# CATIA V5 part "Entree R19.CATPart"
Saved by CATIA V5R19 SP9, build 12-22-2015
Part number: entree
Bounding box of the stored display mesh (mm): x -13.996 to 13.996, y -15 to 21.5, z -13.996 to 13.996
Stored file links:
  C:\Users\hbezard\Documents\Perso\imprimante 3d\pieces\rincepot\Entree R19 - Copie.CATPart
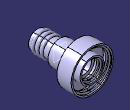
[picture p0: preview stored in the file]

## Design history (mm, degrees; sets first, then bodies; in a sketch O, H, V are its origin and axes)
Parameters
  `dia admi` = 22
  `dia evac` = 10
  `paroies hp` = 2
  `paroies bp` = 2
  `longueur filetee` = 5
  `pas jonction` = 2
  `prof filet jonction` = 1
  `dia gourde` = 12
  `pas gourde` = 2
  `entree gourde` = 8
  `longueur jonction` = 30
  `dia injection` = 8
  `longueur injection` = 110
  `longueur gourde` = 30
  `dia inter injection` = 6
  Real = 0
Body1 (main body)
  Sketch1 on yz-plane, origin (0, 0, 0), H (0, 1, 0), V (0, 0, 1)
    line L1 (-15, 6) -> (-13, 6)
    line L2 (0, 6) -> (0, 8)
    line L3 (16, 8) -> (21.5, 8)
    line L4 (21.5, 8) -> (21.5, 7)
    line L5 (21.5, 7) -> (16, 7)
    line L6 (16, 7) -> (16, 5)
    line L7 (16, 5) -> (0, 5)
    axis line L8 (-32.3822, 0) -> (183.7177, 0)
    line L9 (12, 14) -> (21.5, 14)
    line L10 (21.5, 14) -> (21.5, 13)
    line L11 (21.5, 13) -> (16, 13)
    line L12 (16, 13) -> (16, 8)
    point P13 (-31.9622, 57.8884)
    reference intersected line E1 through (0, 0) direction (-1, 0) from xy-plane
    line L13 (12, 8) -> (0, 8)
    line L14 (0, 5) -> (-15, 5)
    line L15 (-15, 5) -> (-15, 6)
    point P18 (-15, 6)
    line L16 (12, 8) -> (12, 14)
    reference intersected line E2 through (0, 0) direction (0, 1) from zx-plane
    reference intersected line E3 through (0, 0) direction (0, 1) from zx-plane
    arc A1 centre (-12, 6) radius 1 from (-11, 6) to (-13, 6) ccw
    point P20 (-12, 6)
    point P21 (-10, 6)
    point P22 (-8, 6)
    point P23 (-9, 6)
    arc A2 centre (-9, 6) radius 1 from (-8, 6) to (-10, 6) ccw
    point P24 (-7, 6)
    point P25 (-5, 6)
    point P26 (-6, 6)
    arc A3 centre (-6, 6) radius 1 from (-5, 6) to (-7, 6) ccw
    reference intersected line E4 through (0, 0) direction (0, 1) from zx-plane
    line L17 (-5, 6) -> (0, 6)
    line L18 (-8, 6) -> (-7, 6)
    line L19 (-11, 6) -> (-10, 6)
    distance L1 L7 = 1
    distance L7 L8 = 5
    length L5 = 5.5
    distance L3 L5 = 1 {= Sketch1.distance(L1 L7)}
    length L11 = 5.5
    distance L9 L11 = 1 {= `détruit_LENGTH`}
    distance L5 L1 = 1
    distance L9 L3 = 6
    distance L6 E2 = 16
    length L2 = 2
    distance L16 L12 = 4
    radius A1 = 1
    distance L15 P20 = 3
    distance L15 P23 = 6
    distance L15 P26 = 9
    radius A2 = 1
    radius A3 = 1
    distance P25 L1 = 0
    distance P24 L1 = 0
    distance P22 L1 = 0
    distance P21 L1 = 0
    distance L15 E4 = 15
    horizontal: L1 H, L3 H, L5 H, L7 H, L8 H, L9 H, L11 H, L14 H, L13 H
    vertical: L4 V, L10 V, L15 V, L16 V, L2 V, L12 V
    parallelism: L6 L2
    coincidence: L8 E1, L10 L4, P18 L1, P18 L15, L2 E3, P20 L1, P23 L1, P26 L1, L1 L17, L1 L18, L1 L19, P25 A3, P24 A3, P22 A2, P21 A2
  Shaft1 "jonction": profile Sketch1, axis Sketch1.L8, angle 360
  Plane1: type Offset, RefPlane xy-plane, Offset 20
  Sketch2 on Plane1, origin (0, 0, 20), H (1, 0, 0), V (0, 1, 0)
    point P1 (0, 15)
    reference intersected line E1 through (0, 0) direction (0, 1) from yz-plane
    reference intersected line E2 through (0, 0) direction (-1, 0) from zx-plane
    circle A1 centre (0, 15) radius 3
    distance P1 E2 = 15
    radius A1 = 3
    coincidence: P1 E1
  Pocket1: profile unresolved, up to face of Shaft1, deactivated
  Pad1: profile Sketch2, direction (0, 0, -1), up to face of Shaft1 from Sketch1.L3, opposite side length 100, deactivated
  Sketch3 on Plane1, origin (0, 0, 20), H (1, 0, 0), V (0, 1, 0)
    circle A1 centre (0, 15) radius 2
    reference projected point E1 (0, 15) from axis of face of Pad1 from Sketch2.A1
    reference projected circle E2 centre (0, 15) radius 3 from Sketch2.A1
    distance A1 E2 = 1
    concentricity: A1 E1
  Pocket2: profile Sketch3, direction (0, 0, -1), through (limit type 6), opposite side length 98, deactivated
  Plane2: type Angle, RefPlane yz-plane, Direction Y axis, Angle -30
  Plane3: type Offset, RefPlane {inverselocal InverseElem Plane2}, Offset 10, reversed
  Sketch4 on Plane3, origin (-4.0798, 0, 27.0665), H (0, -1, 0), V (-0.5, 0, 0.866)
    line L1 (-18.1996, -23.9802) -> (-19.5373, -23.9802)
    line L2 (-19.5373, -23.9802) -> (-19.5373, -26.9802)
    line L3 (-19.5373, -26.9802) -> (-18.1996, -26.9802)
    line L4 (-18.1996, -26.9802) -> (-18.1996, -23.9802)
    point P5 (-24, -23.9802)
    line L5 (-24, -23.9802) -> (-22.6623, -23.9802)
    line L6 (-22.6623, -23.9802) -> (-22.6623, -26.9802)
    line L7 (-22.6623, -26.9802) -> (-24, -26.9802)
    line L8 (-24, -26.9802) -> (-24, -23.9802)
    point P7 (-22.6623, -26.9802)
    reference intersected line E1 through (-12.1996, 0) direction (0, -1) from face of Shaft1
    reference intersected line E2 through (-30, 0) direction (0, -1) from face of Shaft1 from Sketch1.L10
    reference projected line E3 through (0, -25.4802) direction (-1, 0) from axis of face of Shaft1 from Sketch1.L7
    length L3 = 1.3377
    length L7 = 1.3377 {= Sketch4.length(L3)}
    distance L3 L1 = 3
    distance L4 E1 = 6
    distance L8 E2 = 6
    horizontal: L1 H, L3 H, L5 H, L7 H
    vertical: L2 V, L4 V, L6 V, L8 V
    coincidence: P5 L1, P7 L3
    symmetry: L3 L1 E3
  Pad2: profile Sketch4, direction (-0.866, 0, -0.5), up to face of Shaft1 from Sketch1.L3, opposite side up to face of Shaft1, deactivated
  Mirror1: of Pad2, about yz-plane, deactivated
  Plane4: type Offset, RefPlane xy-plane, Offset 10, reversed
  Sketch5 on Plane4, origin (0, 0, -10), H (1, 0, 0), V (0, 1, 0)
    point P1 (0, 20.1996)
    line L1 (1, 22.1996) -> (1, 18.1996)
    line L2 (1, 18.1996) -> (-1, 18.1996)
    line L3 (-1, 18.1996) -> (-1, 22.1996)
    line L4 (-1, 22.1996) -> (1, 22.1996)
    point P6 (0, 22)
    line L5 (1, 24) -> (1, 20)
    line L6 (1, 20) -> (-1, 20)
    line L7 (-1, 20) -> (-1, 24)
    line L8 (-1, 24) -> (1, 24)
    point P8 (1, 20)
    reference projected line E1 through (0, 0) direction (0, 1) from axis of face of Shaft1 from Sketch1.L7
    reference intersected line E2 through (0, 12.1996) direction (-1, 0) from face of Shaft1
    reference projected line E3 (-13, 30) -> (13, 30) from edge [face of Shaft1 from Sketch1.L9 | face of Shaft1 from Sketch1.L10]
    length L3 = 4
    length L7 = 4 {= Sketch5.length(L3)}
    length L4 = 2
    distance L2 E2 = 6
    distance L8 E3 = 6
    vertical: L1 V, L3 V, L5 V, L7 V
    horizontal: L2 H, L4 H, L6 H, L8 H
    equidistance: L1 L3 P1, L2 L4 P1, L5 L7 P6, L6 L8 P6
    coincidence: P8 L1, P1 E1, L7 L3
  Pad3: profile Sketch5, direction (0, 0, 1), up to face of Shaft1 from Sketch1.L3, opposite side up to face of Shaft1, deactivated
  Fillet1: radius 0.5, on face of Pad3 from Sketch5.L2; face of Pad3 from Sketch5.L1; face of Pad3 from Sketch5.L3; face of Pad3 from Sketch5.L4; face of Pad3 from Sketch5.L8; face of Pad3 from Sketch5.L5; face of Pad3 from Sketch5.L6; face of Pad3 from Sketch5.L7, deactivated
  Fillet2: radius 0.5, on face of Pad2 from Sketch4.L8; face of Pad2 from Sketch4.L7; face of Pad2 from Sketch4.L5; face of Pad2 from Sketch4.L6; face of Pad2 from Sketch4.L4; face of Pad2 from Sketch4.L3; face of Pad2 from Sketch4.L1; face of Pad2 from Sketch4.L2; face of Mirror1 (x8), deactivated
  Fillet3: radius 0.5, on edge [face of Shaft1 from Sketch1.L3 | face of Pad1 from Sketch2.A1], deactivated
  Helix1: Direction Y axis, RefPoint {point type Coord, X 0, Y -1.155, Z 0, RefPoint vertex [element of Sketch1 | element of Sketch1]}, Pitch 2, Height 3.5, TaperAngle 0
  Sketch6 on yz-plane, origin (0, 0, 0), H (0, 1, 0), V (0, 0, 1)
    point P1 (3.7679, 12)
    line L1 (3.7679, 12) -> (4.9226, 12)
    point P2 (4.9226, 12)
    line L2 (4.9226, 12) -> (4.3453, 13)
    point P3 (4.3453, 13)
    line L3 (4.3453, 13) -> (3.7679, 12)
    axis line L4 (4.3453, 15.5745) -> (4.3453, 9.1301)
    reference projected line E1 (5.5, 12) -> (0, 12) from edge of Sketch1
    reference projected line E2 (5.5, 14) -> (5.5, -14) from edge [face of Shaft1 | face of Shaft1 from Sketch1.L9]
    length L4 = 6.4444
    angle L2 L1 = 60
    distance L1 P3 = 1
    distance L1 E1 = 0
    distance L4 E2 = 1.1547 {= Sketch6.length(L1)}
    length L1 = 1.1547 (reference)
    horizontal: L1 H
    vertical: L4 V
    symmetry: P2 P1 L4
    coincidence: P3 L4
  Rib1: profile Sketch6, centre curve Helix1, deactivated
  Fillet4: radius 0.5, on face of Rib1, deactivated
  Fillet5: radius 0.5, on face of Rib1, deactivated
  Helix2: Direction Y axis, RefPoint vertex [element of Sketch1 | element of Sketch1], Pitch 2, Height 4, TaperAngle 0
  Sketch7 on yz-plane, origin (0, 0, 0), H (0, 1, 0), V (0, 0, 1)
    point P1 (0, 6)
    line L1 (0, 6) -> (1.1547, 6)
    point P2 (1.1547, 6)
    line L2 (1.1547, 6) -> (0.5774, 7)
    point P3 (0.5774, 7)
    line L3 (0.5774, 7) -> (0, 6)
    axis line L4 (0.5774, 18.6338) -> (0.5774, 12.1894)
    reference projected point E1 (0, 6) from vertex [element of Sketch1 | element of Sketch1]
    length L4 = 6.4444
    angle L2 L1 = 60
    distance L1 P3 = 1
    horizontal: L1 H
    vertical: L4 V
    symmetry: P2 P1 L4
    coincidence: P3 L4, P1 E1
  Rib2: profile Sketch7, centre curve Helix2, deactivated
  Fillet6: radius 0.5, on face of Rib2, deactivated
  Fillet7: radius 0.5, on face of Rib2, deactivated
  Sketch8 on yz-plane, origin (0, 0, 0), H (0, 1, 0), V (0, 0, 1)
    point P1 (21.5, 13)
    line L1 (21.5, 13) -> (20.3453, 13)
    point P2 (20.3453, 13)
    line L2 (20.3453, 13) -> (20.9226, 12)
    point P3 (20.9226, 12)
    line L3 (20.9226, 12) -> (21.5, 13)
    axis line L4 (20.9226, 19.8788) -> (20.9226, 13.4344)
    reference projected point E1 (21.5, 13) from vertex [element of Sketch1 | element of Sketch1]
    length L4 = 6.4444
    angle L2 L1 = 60
    distance L1 P3 = 1
    horizontal: L1 H
    vertical: L4 V
    symmetry: P2 P1 L4
    coincidence: P3 L4, P1 E1
  Sketch9 on yz-plane, origin (0, 0, 0), H (0, 1, 0), V (0, 0, 1)
    point P1 (21.5, 7)
    line L1 (21.5, 7) -> (20.3453, 7)
    point P2 (20.3453, 7)
    line L2 (20.3453, 7) -> (20.9226, 6)
    point P3 (20.9226, 6)
    line L3 (20.9226, 6) -> (21.5, 7)
    axis line L4 (20.9226, 13.8788) -> (20.9226, 7.4344)
    reference projected point E1 (21.5, 7) from vertex [element of Sketch1 | element of Sketch1]
    length L4 = 6.4444
    angle L2 L1 = 60
    distance L1 P3 = 1
    horizontal: L1 H
    vertical: L4 V
    symmetry: P2 P1 L4
    coincidence: P3 L4, P1 E1
  Helix3: Direction Y axis, RefPoint vertex [element of Sketch1 | element of Sketch1], Pitch 2, Height 4, TaperAngle 0
  Helix4: Direction Y axis, RefPoint vertex [element of Sketch1 | element of Sketch1], Pitch 2, Height 4, TaperAngle 0
  Rib3: profile Sketch8, centre curve Helix3
  Rib4: profile Sketch9, centre curve Helix4
  Fillet8: radius 0.5, on face of Rib3
  Fillet9: radius 0.5, on face of Rib4
  Fillet10: radius 0.5, on face of Rib4
  Fillet11: radius 0.5, on face of Rib3
  Sketch10 on start face of Pad1, origin (0, 0, 120), H (1, 0, 0), V (0, 1, 0)
    point P1 (0, 0)
  Hole1: placed by Sketch10, at (0, 15, 120) direction (0, 0, -1), diameter 1, through (limit type 6), deactivated
  Point1: type OnCurve, Support edge [face of Pad1 from Sketch2.A1 | start face of Pad1], RefPoint {extremum Reference edge [face of Pad1 from Sketch2.A1 | start face of Pad1], Direction (1, 2, 3)}, Ratio 0.5
  Sketch11 on yz-plane, origin (0, -0.7113, -0.4445), H (0, 1, 0), V (0, 0, 1)
    point P1 (15.7113, 116.4445)
    reference projected line E1 through (15.7113, 0) direction (0, 1) from axis of face of Pad1 from Sketch2.A1
    reference intersected line E2 (12.7113, 120.4445) -> (18.7113, 120.4445) from start face of Pad1
    distance P1 E2 = 4
    coincidence: P1 E1
  Hole2: placed by Sketch11, at (0, 15, 116) direction (-1, 0, 0), diameter 1, through (limit type 3), deactivated
  CircPattern1: of Hole2, instances 8, angular step 45, deactivated
  RectPattern1: of CircPattern1, direction 1 instances 10, spacing 9, along Z axis reversed, deactivated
